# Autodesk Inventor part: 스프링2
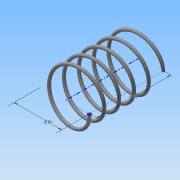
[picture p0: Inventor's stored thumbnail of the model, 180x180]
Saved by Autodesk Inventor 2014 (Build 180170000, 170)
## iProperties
Created: 2015-06
Part Number: 스프링2
Material: 강철, 연강
Document SubType Name: Modeling
Designer: MYHOME
Density: 7.86 g/cm^3
Appearance: 강철
Mass: 1.52988 g
Surface Area: 7.87024 cm^2
Volume: 0.194641 cm^3
Author: MYHOME
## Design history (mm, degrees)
sketch "스케치1"
  geometry: L1 (0, 0)-(8, 0); L2 (8, 0)-(8, 14.5); L3 (8, 14.5)-(0, 14.5); L4 (0, 14.5)-(0, 0); C1 r 0.5 at (8, 0)
  constraints: 8 end point, 2 parallel, 1 centre point, 1 coincident, 1 horizontal, 1 perpendicular
  dimensions: "d0" = 16 diameter of L2 L4; "d1" = 14.5 distance of L1.end L2.end (derived); "d2" = 1 diameter of C1
feature "코일2" sketch "스케치1" pitch "d17" = 10; turns "d19" = 5; dims "d18" = 14.5 (= d1), "d20" = 0, angle "d21" = 90 deg, angle "d22" = 90 deg, "d23" = 0, "d24" = 0
node "작업 평면3"
sketch "스케치4"
  geometry: L1 (-8.5, 0)-(-7.5, 0) reference; 1 further point
  constraints: 1 horizontal alignment
extrude "돌출3" cut sketch "스케치4" stored distance "d26" = 10; taper "d27" = 0 deg
node "작업 평면4"
sketch "스케치5"
  geometry: L1 (-7.5, 0)-(-8.5, 0) reference; 1 further point
  constraints: 1 horizontal alignment
extrude "돌출4" cut sketch "스케치5" stored distance "d29" = 10; taper "d30" = 0 deg
node "솔리드2"
node "절단 모서리 투영3"
node "절단 모서리 투영4"
other parameters: "d25" = 0, "d28" = 14.5 (= d1)
